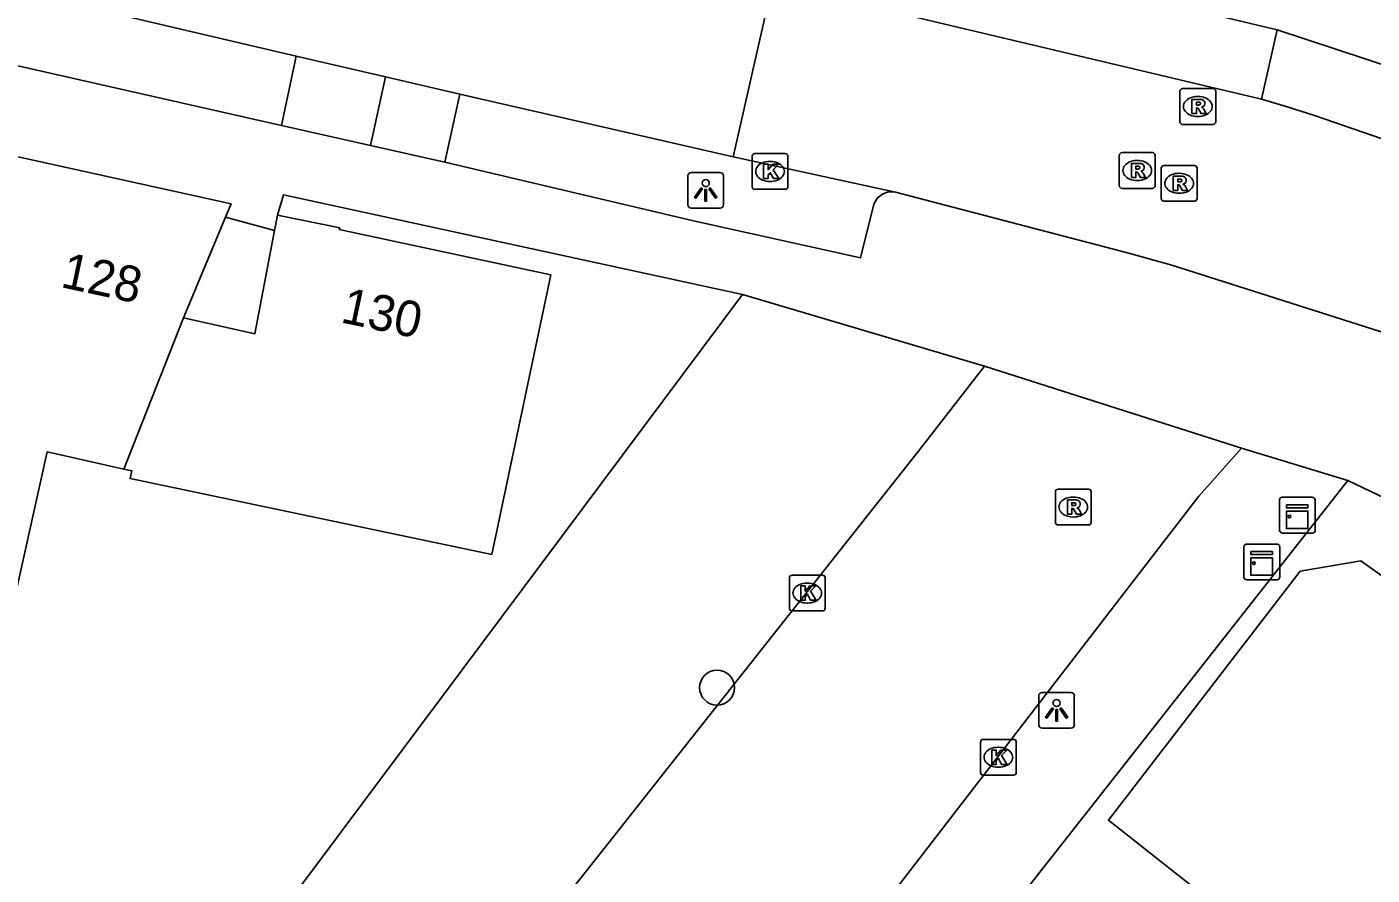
# Model space of a CAD drawing. Extents: x 159888 to 160757, y 384031 to 384746.
# Drawn here: x 160350.64 to 160388.28, y 384428 to 384451.74 of the extents above; entities that cross this region are included whole.
import ezdxf

# ---------------------------------------------------------------- set-up
doc = ezdxf.new("R2010")
doc.units = 0
for name, color, linetype in [('IMGEO_Boom', 7, 'Continuous'), ('IMGEO_Kast', 7, 'Continuous'), ('IMGEO_Kolk', 7, 'Continuous'), ('IMGEO_Lichtpunt', 7, 'Continuous'), ('IMGEO_Pand', 7, 'Continuous'), ('IMGEO_Pand_nummerreeks', 7, 'Continuous'), ('IMGEO_Parkeervlak_open', 7, 'Continuous'), ('IMGEO_Rijbaan_lokaal_open', 7, 'Continuous'), ('IMGEO_Rioolput', 7, 'Continuous'), ('IMGEO_Voetpad_open', 7, 'Continuous')]:
    doc.layers.add(name, color=color, linetype=linetype)

msp = doc.modelspace()

# ---------------------------------------------------------------- linework, layer by layer
at = {"layer": 'IMGEO_Boom'}
msp.add_circle((160369.95, 384433.245), 0.489, dxfattribs=at)
at = {"layer": 'IMGEO_Kast'}
for p, q in [((160385.684, 384437.646), (160385.684, 384438.487)), ((160385.684, 384438.487), (160385.684, 384437.646)), ((160385.759, 384438.571), (160386.6, 384438.571)), ((160386.6, 384438.571), (160385.759, 384438.571)), ((160386.684, 384438.496), (160386.684, 384437.655)), ((160386.684, 384437.655), (160386.684, 384438.496)), ((160384.767, 384437.263), (160385.608, 384437.263)), ((160385.608, 384437.263), (160384.767, 384437.263)), ((160386.609, 384437.571), (160385.768, 384437.571)), ((160385.768, 384437.571), (160386.609, 384437.571)), ((160384.692, 384436.338), (160384.692, 384437.179)), ((160384.692, 384437.179), (160384.692, 384436.338)), ((160385.692, 384437.188), (160385.692, 384436.347)), ((160385.692, 384436.347), (160385.692, 384437.188)), ((160385.617, 384436.263), (160384.776, 384436.263)), ((160384.776, 384436.263), (160385.617, 384436.263))]:
    msp.add_line(p, q, dxfattribs=at)
for points in [[(160385.879, 384438.361), (160386.479, 384438.361), (160386.479, 384438.276), (160385.879, 384438.276), (160385.879, 384438.361)], [(160385.879, 384438.186), (160386.479, 384438.186), (160386.479, 384437.697), (160385.879, 384437.697), (160385.879, 384438.186)], [(160384.887, 384437.053), (160385.487, 384437.053), (160385.487, 384436.968), (160384.887, 384436.968), (160384.887, 384437.053)], [(160384.887, 384436.878), (160385.487, 384436.878), (160385.487, 384436.389), (160384.887, 384436.389), (160384.887, 384436.878)]]:
    msp.add_lwpolyline(points, dxfattribs=at)
for centre in [(160385.963, 384438.035), (160384.971, 384436.727)]:
    msp.add_circle(centre, 0.0377, dxfattribs=at)
for centre, start, end in [((160385.762, 384438.493), 92.4484, 184.2845), ((160385.762, 384438.493), 92.4484, 184.2845), ((160386.606, 384438.493), 2.4484, 94.2845), ((160386.606, 384438.493), 2.4484, 94.2845), ((160385.762, 384437.649), 182.4484, 274.2845), ((160385.762, 384437.649), 182.4484, 274.2845), ((160386.606, 384437.649), 272.4484, 4.2845), ((160386.606, 384437.649), 272.4484, 4.2845), ((160384.77, 384437.185), 92.4484, 184.2845), ((160384.77, 384437.185), 92.4484, 184.2845), ((160385.614, 384437.185), 2.4484, 94.2845), ((160385.614, 384437.185), 2.4484, 94.2845), ((160384.77, 384436.341), 182.4484, 274.2845), ((160384.77, 384436.341), 182.4484, 274.2845), ((160385.614, 384436.341), 272.4484, 4.2845), ((160385.614, 384436.341), 272.4484, 4.2845)]:
    msp.add_arc(centre, 0.0779, start, end, dxfattribs=at)
at = {"layer": 'IMGEO_Kolk'}
for p, q in [((160371.006, 384448.191), (160371.858, 384448.191)), ((160370.931, 384447.265), (160370.931, 384448.117)), ((160371.419, 384447.971), (160371.444, 384447.971)), ((160371.932, 384448.117), (160371.932, 384447.265)), ((160371.442, 384447.411), (160371.417, 384447.411)), ((160371.858, 384447.191), (160371.006, 384447.191)), ((160371.973, 384435.465), (160371.973, 384436.317)), ((160372.048, 384436.391), (160372.9, 384436.391)), ((160372.461, 384436.171), (160372.486, 384436.171)), ((160372.974, 384436.317), (160372.974, 384435.465)), ((160372.9, 384435.391), (160372.048, 384435.391)), ((160372.484, 384435.611), (160372.459, 384435.611)), ((160377.318, 384430.868), (160377.318, 384431.72)), ((160377.393, 384431.794), (160378.245, 384431.794)), ((160377.806, 384431.574), (160377.831, 384431.574)), ((160378.319, 384431.72), (160378.319, 384430.868)), ((160377.829, 384431.014), (160377.804, 384431.014)), ((160378.245, 384430.794), (160377.393, 384430.794))]:
    msp.add_line(p, q, dxfattribs=at)
for points in [[(160371.006, 384448.191), (160371.858, 384448.191)], [(160370.931, 384447.265), (160370.931, 384448.117)], [(160371.252, 384447.891), (160371.375, 384447.891), (160371.375, 384447.74), (160371.505, 384447.891), (160371.669, 384447.891), (160371.523, 384447.74), (160371.676, 384447.491), (160371.524, 384447.491), (160371.439, 384447.655), (160371.375, 384447.588), (160371.375, 384447.491), (160371.252, 384447.491), (160371.252, 384447.891)], [(160371.932, 384448.117), (160371.932, 384447.265)], [(160371.858, 384447.191), (160371.006, 384447.191)], [(160371.973, 384435.465), (160371.973, 384436.317)], [(160372.048, 384436.391), (160372.9, 384436.391)], [(160372.294, 384436.091), (160372.417, 384436.091), (160372.417, 384435.94), (160372.547, 384436.091), (160372.711, 384436.091), (160372.565, 384435.94), (160372.718, 384435.691), (160372.566, 384435.691), (160372.481, 384435.855), (160372.417, 384435.788), (160372.417, 384435.691), (160372.294, 384435.691), (160372.294, 384436.091)], [(160372.974, 384436.317), (160372.974, 384435.465)], [(160372.9, 384435.391), (160372.048, 384435.391)], [(160377.318, 384430.868), (160377.318, 384431.72)], [(160377.393, 384431.794), (160378.245, 384431.794)], [(160378.319, 384431.72), (160378.319, 384430.868)], [(160377.639, 384431.494), (160377.762, 384431.494), (160377.762, 384431.343), (160377.892, 384431.494), (160378.056, 384431.494), (160377.91, 384431.343), (160378.063, 384431.094), (160377.911, 384431.094), (160377.826, 384431.258), (160377.762, 384431.191), (160377.762, 384431.094), (160377.639, 384431.094), (160377.639, 384431.494)], [(160378.245, 384430.794), (160377.393, 384430.794)]]:
    msp.add_lwpolyline(points, dxfattribs=at)
for centre, start, end in [((160371.008, 384448.115), 91.552, 178.448), ((160371.008, 384448.115), 91.552, 178.448), ((160371.856, 384448.115), 1.552, 88.448), ((160371.856, 384448.115), 1.552, 88.448), ((160371.008, 384447.267), 181.552, 268.448), ((160371.008, 384447.267), 181.552, 268.448), ((160371.856, 384447.267), 271.552, 358.448), ((160371.856, 384447.267), 271.552, 358.448), ((160372.05, 384436.315), 91.552, 178.448), ((160372.05, 384436.315), 91.552, 178.448), ((160372.898, 384436.315), 1.552, 88.448), ((160372.898, 384436.315), 1.552, 88.448), ((160372.05, 384435.467), 181.552, 268.448), ((160372.05, 384435.467), 181.552, 268.448), ((160372.898, 384435.467), 271.552, 358.448), ((160372.898, 384435.467), 271.552, 358.448), ((160377.395, 384431.718), 91.552, 178.448), ((160377.395, 384431.718), 91.552, 178.448), ((160378.243, 384431.718), 1.552, 88.448), ((160378.243, 384431.718), 1.552, 88.448), ((160377.395, 384430.87), 181.552, 268.448), ((160377.395, 384430.87), 181.552, 268.448), ((160378.243, 384430.87), 271.552, 358.448), ((160378.243, 384430.87), 271.552, 358.448)]:
    msp.add_arc(centre, 0.0765, start, end, dxfattribs=at)
for centre, major_axis, ratio, start_param, end_param in [((160371.418, 384447.691), (-0.387, 0.002), 0.722429, 4.712389, 7.853982), ((160371.443, 384447.691), (-0.39, 0.002), 0.717154, 1.570796, 4.712389), ((160372.46, 384435.891), (-0.387, 0.002), 0.722429, 4.712389, 7.853982), ((160372.485, 384435.891), (-0.39, 0.002), 0.717154, 1.570796, 4.712389), ((160377.805, 384431.294), (-0.387, 0.002), 0.722429, 4.712389, 7.853982), ((160377.83, 384431.294), (-0.39, 0.002), 0.717154, 1.570796, 4.712389)]:
    msp.add_ellipse(centre, major_axis=major_axis, ratio=ratio, start_param=start_param, end_param=end_param, dxfattribs=at)
at = {"layer": 'IMGEO_Lichtpunt'}
for p, q in [((160369.133, 384447.568), (160369.133, 384446.761)), ((160369.133, 384447.568), (160369.133, 384446.761)), ((160370.035, 384447.663), (160369.227, 384447.663)), ((160370.035, 384447.663), (160369.227, 384447.663)), ((160370.129, 384446.761), (160370.129, 384447.568)), ((160370.129, 384446.761), (160370.129, 384447.568)), ((160369.227, 384446.667), (160370.035, 384446.667)), ((160369.227, 384446.667), (160370.035, 384446.667)), ((160379.851, 384433.109), (160379.043, 384433.109)), ((160379.851, 384433.109), (160379.043, 384433.109)), ((160378.949, 384433.014), (160378.949, 384432.207)), ((160378.949, 384433.014), (160378.949, 384432.207)), ((160379.945, 384432.207), (160379.945, 384433.014)), ((160379.945, 384432.207), (160379.945, 384433.014)), ((160379.043, 384432.113), (160379.851, 384432.113)), ((160379.043, 384432.113), (160379.851, 384432.113))]:
    msp.add_line(p, q, dxfattribs=at)
for points in [[(160369.507, 384447.232), (160369.546, 384447.204), (160369.358, 384446.942), (160369.32, 384446.969), (160369.507, 384447.232)], [(160369.609, 384447.184), (160369.656, 384447.184), (160369.656, 384446.862), (160369.609, 384446.862), (160369.609, 384447.184)], [(160369.719, 384447.204), (160369.757, 384447.231), (160369.944, 384446.969), (160369.905, 384446.941), (160369.719, 384447.204)], [(160379.323, 384432.678), (160379.362, 384432.65), (160379.174, 384432.388), (160379.136, 384432.415), (160379.323, 384432.678)], [(160379.425, 384432.63), (160379.472, 384432.63), (160379.472, 384432.308), (160379.425, 384432.308), (160379.425, 384432.63)], [(160379.535, 384432.65), (160379.573, 384432.677), (160379.76, 384432.415), (160379.721, 384432.387), (160379.535, 384432.65)]]:
    msp.add_lwpolyline(points, dxfattribs=at)
for centre in [(160369.632, 384447.366), (160379.448, 384432.812)]:
    msp.add_circle(centre, 0.0994, dxfattribs=at)
for centre, start, end in [((160369.227, 384447.568), 90, 180), ((160369.227, 384447.568), 90, 180), ((160370.035, 384447.568), 0, 90), ((160370.035, 384447.568), 0, 90), ((160369.227, 384446.761), 180, 270), ((160369.227, 384446.761), 180, 270), ((160370.035, 384446.761), 270, 0), ((160370.035, 384446.761), 270, 360), ((160379.043, 384433.014), 90, 180), ((160379.043, 384433.014), 90, 180), ((160379.851, 384433.014), 0, 90), ((160379.851, 384433.014), 0, 90), ((160379.043, 384432.207), 180, 270), ((160379.043, 384432.207), 180, 270), ((160379.851, 384432.207), 270, 0), ((160379.851, 384432.207), 270, 360)]:
    msp.add_arc(centre, 0.0946, start, end, dxfattribs=at)
at = {"layer": 'IMGEO_Pand'}
for points in [[(160356.191, 384446.408), (160356.349, 384446.788), (160350.646, 384448.041), (160350.38, 384448.096)], [(160353.348, 384439.36), (160353.571, 384439.31), (160353.526, 384439.095), (160363.645, 384436.973), (160365.295, 384444.799), (160359.38, 384446.067), (160359.39, 384446.116), (160357.646, 384446.468)], [(160356.191, 384446.408), (160355.018, 384443.593)], [(160357.646, 384446.468), (160357.565, 384446.039)], [(160355.018, 384443.593), (160357.02, 384443.149), (160357.565, 384446.039)], [(160355.018, 384443.593), (160353.348, 384439.36)], [(160353.348, 384439.36), (160351.202, 384439.84), (160348.945, 384429.73), (160346.692, 384430.234)], [(160392.752, 384436.58), (160391.848, 384435.413), (160390.547, 384436.352), (160389.885, 384435.424), (160387.964, 384436.795), (160386.264, 384436.508), (160380.897, 384429.533), (160384.235, 384426.903), (160384.589, 384427.381), (160387.592, 384425.346), (160388.64, 384426.892), (160389.786, 384426.116), (160389.24, 384425.31), (160391.429, 384423.585)]]:
    msp.add_lwpolyline(points, dxfattribs=at)
at = {"layer": 'IMGEO_Parkeervlak_open'}
msp.add_lwpolyline([(160362.748, 384449.857), (160362.333, 384447.948)], dxfattribs=at)
at = {"layer": 'IMGEO_Rijbaan_lokaal_open'}
for points in [[(160349.763, 384452.894), (160358.168, 384450.919)], [(160371.5, 384452.948), (160370.401, 384448.105)], [(160373.287, 384452.54), (160385.18, 384449.716)], [(160358.168, 384450.919), (160357.759, 384448.977)], [(160360.67, 384450.338), (160358.168, 384450.919)], [(160360.254, 384448.416), (160360.67, 384450.338)], [(160362.748, 384449.857), (160360.67, 384450.338)], [(160370.401, 384448.105), (160362.748, 384449.857)], [(160385.18, 384449.716), (160385.874, 384449.509), (160386.663, 384449.261), (160390.723, 384447.86)], [(160357.759, 384448.977), (160360.254, 384448.416)], [(160374.937, 384447.114), (160370.401, 384448.105)], [(160374.937, 384447.114), (160381.429, 384445.418), (160382.675, 384445.072), (160390.376, 384442.615)], [(160364.455, 384425.797), (160375.615, 384439.899), (160377.432, 384442.237)], [(160377.432, 384442.237), (160384.622, 384439.943)], [(160384.622, 384439.943), (160383.429, 384438.604), (160373.655, 384425.921), (160370.72, 384422.188)]]:
    msp.add_lwpolyline(points, dxfattribs=at)
at = {"layer": 'IMGEO_Rioolput'}
for p, q in [((160382.9, 384449.083), (160382.9, 384449.935)), ((160382.975, 384450.009), (160383.827, 384450.009)), ((160383.388, 384449.789), (160383.413, 384449.789)), ((160383.901, 384449.935), (160383.901, 384449.083)), ((160383.827, 384449.009), (160382.975, 384449.009)), ((160383.411, 384449.229), (160383.386, 384449.229)), ((160381.204, 384447.292), (160381.204, 384448.144)), ((160381.279, 384448.218), (160382.131, 384448.218)), ((160382.205, 384448.144), (160382.205, 384447.292)), ((160381.692, 384447.998), (160381.717, 384447.998)), ((160382.378, 384446.933), (160382.378, 384447.785)), ((160382.453, 384447.859), (160383.305, 384447.859)), ((160383.379, 384447.785), (160383.379, 384446.933)), ((160381.715, 384447.438), (160381.69, 384447.438)), ((160382.866, 384447.639), (160382.891, 384447.639)), ((160382.131, 384447.218), (160381.279, 384447.218)), ((160382.889, 384447.079), (160382.864, 384447.079)), ((160383.305, 384446.859), (160382.453, 384446.859)), ((160379.414, 384437.873), (160379.414, 384438.725)), ((160379.489, 384438.799), (160380.341, 384438.799)), ((160380.415, 384438.725), (160380.415, 384437.873)), ((160379.902, 384438.579), (160379.927, 384438.579)), ((160379.925, 384438.019), (160379.9, 384438.019)), ((160380.341, 384437.799), (160379.489, 384437.799))]:
    msp.add_line(p, q, dxfattribs=at)
for points in [[(160382.9, 384449.083), (160382.9, 384449.935)], [(160382.975, 384450.009), (160383.827, 384450.009)], [(160383.489, 384449.707), (160383.237, 384449.709), (160383.237, 384449.309)], [(160383.901, 384449.935), (160383.901, 384449.083)], [(160383.237, 384449.309), (160383.361, 384449.309), (160383.361, 384449.471), (160383.372, 384449.471)], [(160383.415, 384449.628), (160383.361, 384449.628), (160383.361, 384449.547)], [(160383.361, 384449.547), (160383.413, 384449.547)], [(160383.419, 384449.442), (160383.49, 384449.309), (160383.63, 384449.309), (160383.565, 384449.435)], [(160383.827, 384449.009), (160382.975, 384449.009)], [(160381.204, 384447.292), (160381.204, 384448.144)], [(160381.279, 384448.218), (160382.131, 384448.218)], [(160382.205, 384448.144), (160382.205, 384447.292)], [(160381.793, 384447.916), (160381.541, 384447.918), (160381.541, 384447.518)], [(160381.719, 384447.837), (160381.665, 384447.837), (160381.665, 384447.756)], [(160381.665, 384447.756), (160381.717, 384447.756)], [(160382.378, 384446.933), (160382.378, 384447.785)], [(160382.453, 384447.859), (160383.305, 384447.859)], [(160383.379, 384447.785), (160383.379, 384446.933)], [(160381.541, 384447.518), (160381.665, 384447.518), (160381.665, 384447.68), (160381.676, 384447.68)], [(160381.723, 384447.651), (160381.794, 384447.518), (160381.934, 384447.518), (160381.869, 384447.644)], [(160382.967, 384447.557), (160382.715, 384447.559), (160382.715, 384447.159)], [(160382.893, 384447.478), (160382.839, 384447.478), (160382.839, 384447.397)], [(160382.839, 384447.397), (160382.891, 384447.397)], [(160382.131, 384447.218), (160381.279, 384447.218)], [(160382.715, 384447.159), (160382.839, 384447.159), (160382.839, 384447.321), (160382.85, 384447.321)], [(160382.897, 384447.292), (160382.968, 384447.159), (160383.108, 384447.159), (160383.043, 384447.285)], [(160383.305, 384446.859), (160382.453, 384446.859)], [(160379.414, 384437.873), (160379.414, 384438.725)], [(160379.489, 384438.799), (160380.341, 384438.799)], [(160380.415, 384438.725), (160380.415, 384437.873)], [(160380.003, 384438.497), (160379.751, 384438.499), (160379.751, 384438.099)], [(160379.929, 384438.418), (160379.875, 384438.418), (160379.875, 384438.337)], [(160379.751, 384438.099), (160379.875, 384438.099), (160379.875, 384438.261), (160379.886, 384438.261)], [(160379.875, 384438.337), (160379.927, 384438.337)], [(160379.933, 384438.232), (160380.004, 384438.099), (160380.144, 384438.099), (160380.079, 384438.225)], [(160380.341, 384437.799), (160379.489, 384437.799)]]:
    msp.add_lwpolyline(points, dxfattribs=at)
for centre, radius, start, end in [((160382.977, 384449.933), 0.0765, 91.552, 178.448), ((160382.977, 384449.933), 0.0765, 91.552, 178.448), ((160383.488, 384449.597), 0.109, 350.3612, 89.416), ((160383.825, 384449.933), 0.0765, 1.552, 88.448), ((160383.825, 384449.933), 0.0765, 1.552, 88.448), ((160383.371, 384449.418), 0.0533, 26.0293, 88.6989), ((160383.397, 384449.736), 0.19, 274.7715, 282.9687), ((160383.421, 384449.532), 0.0964, 77.0061, 93.1865), ((160383.435, 384449.589), 0.0378, 276.6634, 79.6772), ((160383.486, 384449.597), 0.112, 277.5842, 350.9817), ((160383.47, 384449.382), 0.108, 29.5134, 73.7905), ((160382.977, 384449.085), 0.0765, 181.552, 268.448), ((160382.977, 384449.085), 0.0765, 181.552, 268.448), ((160383.825, 384449.085), 0.0765, 271.552, 358.448), ((160383.825, 384449.085), 0.0765, 271.552, 358.448), ((160381.281, 384448.142), 0.0765, 91.552, 178.448), ((160381.281, 384448.142), 0.0765, 91.552, 178.448), ((160382.129, 384448.142), 0.0765, 1.552, 88.448), ((160382.129, 384448.142), 0.0765, 1.552, 88.448), ((160381.701, 384447.945), 0.19, 274.7715, 282.9687), ((160381.725, 384447.741), 0.0964, 77.0061, 93.1865), ((160381.739, 384447.798), 0.0378, 276.6634, 79.6772), ((160381.792, 384447.806), 0.109, 350.3612, 89.416), ((160381.79, 384447.806), 0.112, 277.5842, 350.9817), ((160382.455, 384447.783), 0.0765, 91.552, 178.448), ((160382.455, 384447.783), 0.0765, 91.552, 178.448), ((160383.303, 384447.783), 0.0765, 1.552, 88.448), ((160383.303, 384447.783), 0.0765, 1.552, 88.448), ((160381.675, 384447.627), 0.0533, 26.0293, 88.6989), ((160381.774, 384447.591), 0.108, 29.5134, 73.7905), ((160382.875, 384447.586), 0.19, 274.7715, 282.9687), ((160382.899, 384447.382), 0.0964, 77.0061, 93.1865), ((160382.913, 384447.439), 0.0378, 276.6634, 79.6772), ((160382.966, 384447.447), 0.109, 350.3612, 89.416), ((160382.964, 384447.447), 0.112, 277.5842, 350.9817), ((160381.281, 384447.294), 0.0765, 181.552, 268.448), ((160381.281, 384447.294), 0.0765, 181.552, 268.448), ((160382.129, 384447.294), 0.0765, 271.552, 358.448), ((160382.129, 384447.294), 0.0765, 271.552, 358.448), ((160382.849, 384447.268), 0.0533, 26.0293, 88.6989), ((160382.948, 384447.232), 0.108, 29.5134, 73.7905), ((160382.455, 384446.935), 0.0765, 181.552, 268.448), ((160382.455, 384446.935), 0.0765, 181.552, 268.448), ((160383.303, 384446.935), 0.0765, 271.552, 358.448), ((160383.303, 384446.935), 0.0765, 271.552, 358.448), ((160379.491, 384438.723), 0.0765, 91.552, 178.448), ((160379.491, 384438.723), 0.0765, 91.552, 178.448), ((160380.339, 384438.723), 0.0765, 1.552, 88.448), ((160380.339, 384438.723), 0.0765, 1.552, 88.448), ((160379.935, 384438.322), 0.0964, 77.0061, 93.1865), ((160379.949, 384438.379), 0.0378, 276.6634, 79.6772), ((160380.002, 384438.387), 0.109, 350.3612, 89.416), ((160380, 384438.387), 0.112, 277.5842, 350.9817), ((160379.885, 384438.208), 0.0533, 26.0293, 88.6989), ((160379.911, 384438.526), 0.19, 274.7715, 282.9687), ((160379.984, 384438.172), 0.108, 29.5134, 73.7905), ((160379.491, 384437.875), 0.0765, 181.552, 268.448), ((160379.491, 384437.875), 0.0765, 181.552, 268.448), ((160380.339, 384437.875), 0.0765, 271.552, 358.448), ((160380.339, 384437.875), 0.0765, 271.552, 358.448)]:
    msp.add_arc(centre, radius, start, end, dxfattribs=at)
for centre, major_axis, ratio, start_param, end_param in [((160383.387, 384449.509), (-0.387, 0.002), 0.722429, 4.712389, 7.853982), ((160383.412, 384449.509), (-0.39, 0.002), 0.717154, 1.570796, 4.712389), ((160381.691, 384447.718), (-0.387, 0.002), 0.722429, 4.712389, 7.853982), ((160381.716, 384447.718), (-0.39, 0.002), 0.717154, 1.570796, 4.712389), ((160382.865, 384447.359), (-0.387, 0.002), 0.722429, 4.712389, 7.853982), ((160382.89, 384447.359), (-0.39, 0.002), 0.717154, 1.570796, 4.712389), ((160379.901, 384438.299), (-0.387, 0.002), 0.722429, 4.712389, 7.853982), ((160379.926, 384438.299), (-0.39, 0.002), 0.717154, 1.570796, 4.712389)]:
    msp.add_ellipse(centre, major_axis=major_axis, ratio=ratio, start_param=start_param, end_param=end_param, dxfattribs=at)
at = {"layer": 'IMGEO_Voetpad_open'}
for points in [[(160357.759, 384448.977), (160333.85, 384454.4)], [(160385.623, 384451.658), (160374.125, 384454.397)], [(160385.18, 384449.716), (160385.623, 384451.658)], [(160385.623, 384451.658), (160391.421, 384449.745)], [(160360.254, 384448.416), (160362.333, 384447.948)], [(160362.333, 384447.948), (160369.294, 384446.306), (160373.965, 384445.272), (160374.338, 384446.776)], [(160370.659, 384444.25), (160357.817, 384447.041), (160357.646, 384446.468)], [(160357.565, 384446.039), (160356.191, 384446.408)], [(160352.713, 384420.21), (160370.659, 384444.25)], [(160370.659, 384444.25), (160377.432, 384442.237)], [(160387.602, 384439.041), (160384.622, 384439.943)], [(160387.602, 384439.041), (160372.969, 384420.438)], [(160392.752, 384436.58), (160387.602, 384439.041)]]:
    msp.add_lwpolyline(points, dxfattribs=at)
msp.add_arc((160374.836, 384446.593), 0.531, 79.0316, 159.8382, dxfattribs=at)

# ---------------------------------------------------------------- texts
at = {"layer": 'IMGEO_Pand_nummerreeks'}
for s, rotation, p in [('128', 347.922, (160351.55, 384444.46)), ('130', 348.0653, (160359.385, 384443.474))]:
    msp.add_text(s, height=1, rotation=rotation, dxfattribs=at).set_placement(p)

doc.saveas('drawing.dxf')
